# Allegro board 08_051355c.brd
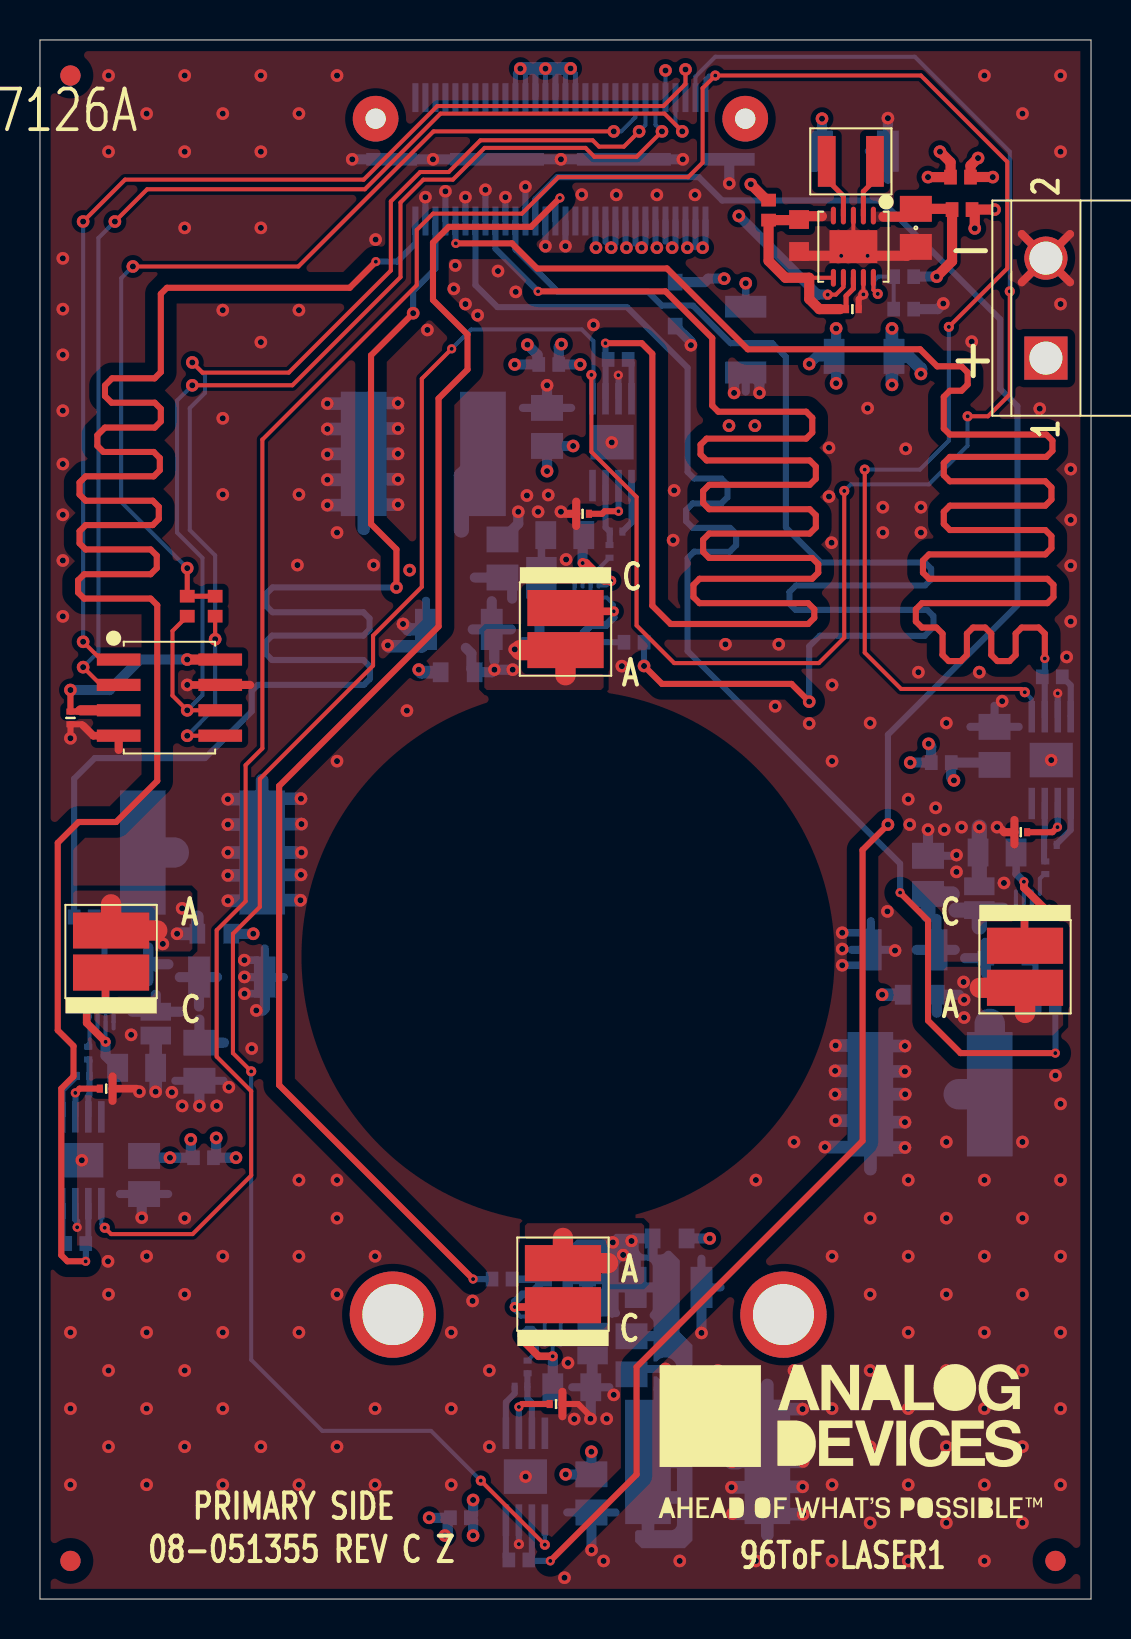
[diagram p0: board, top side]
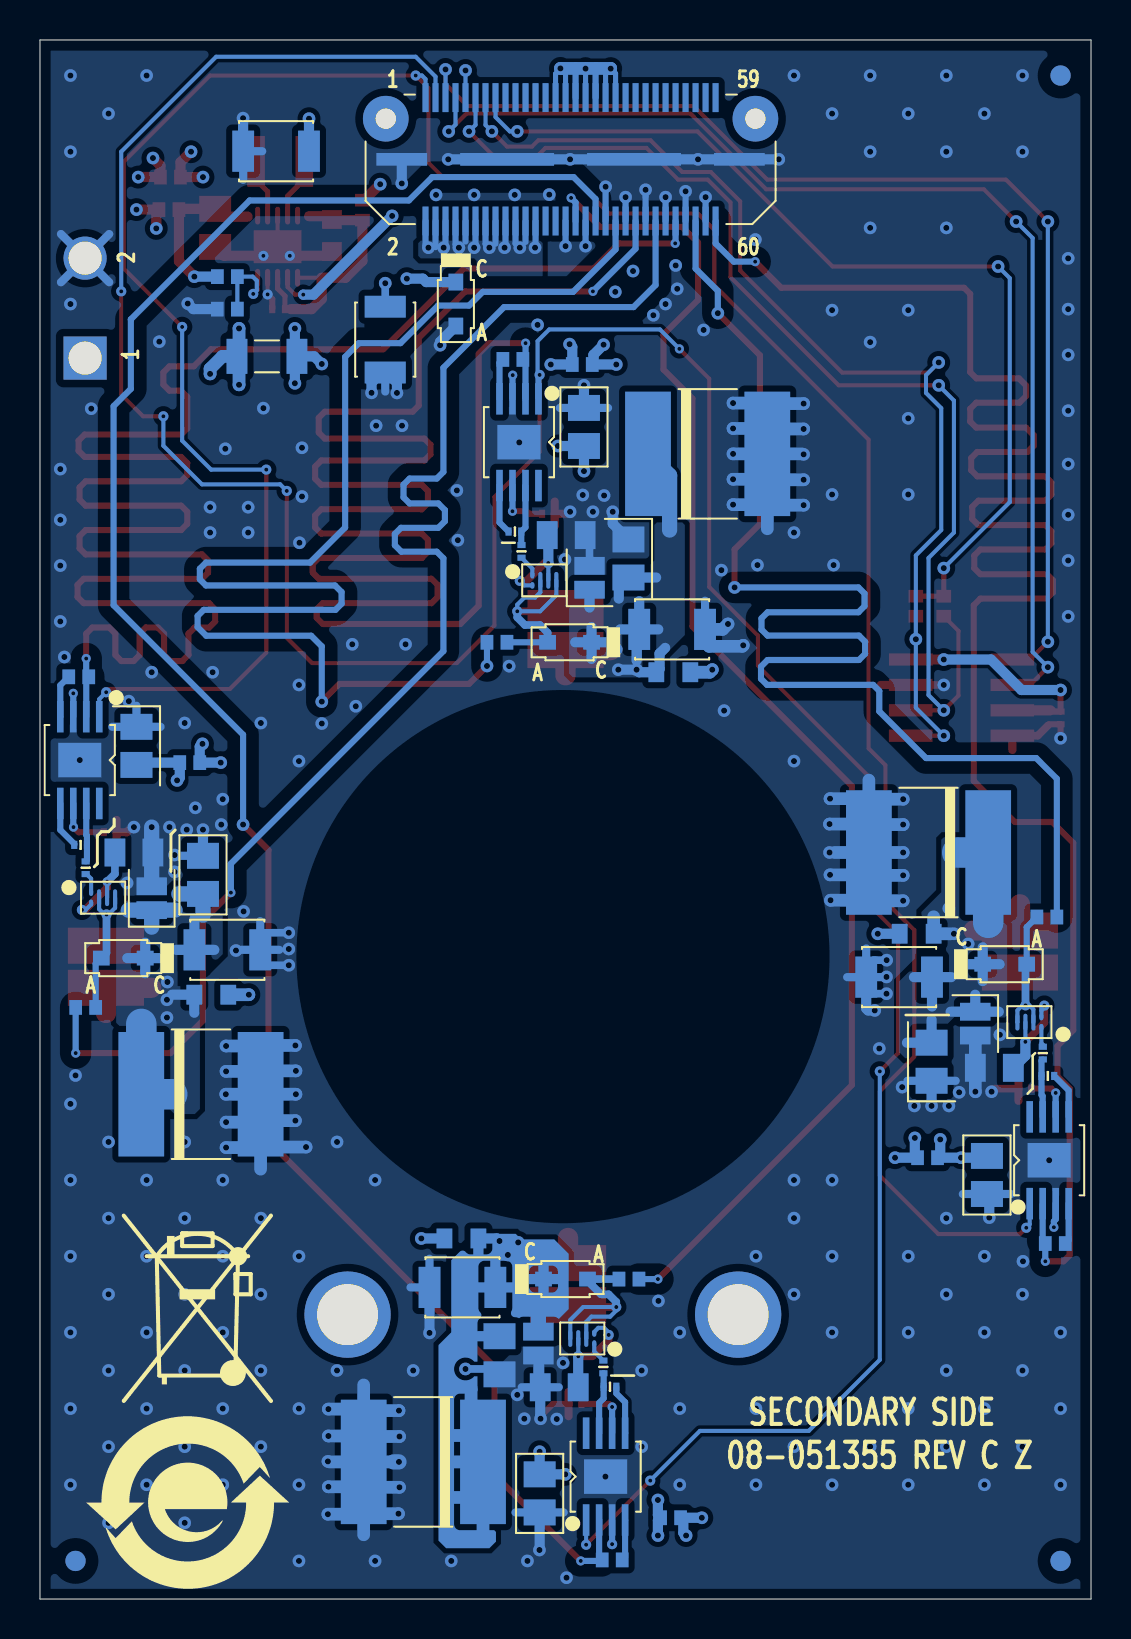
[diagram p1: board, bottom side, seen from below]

Outline 52.58 x 77.98 mm; copper layers: TOP, L2_GND, L3_PWR, L4_PWR, L5_GND, BOTTOM. Coordinates in mm from the lower left corner of the outline.
Outline path: 0,77.98 52.58,77.98 52.58,0 0,0 0,77.98

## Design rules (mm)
constraint set DEFAULT: min track width 0.203
net group TAL: nets TAL1 TAL2 TAL3 TAL4

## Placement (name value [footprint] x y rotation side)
C1  0.1uF  [C0201]  3.31 25.53 180 top
C2  0.1uF  [C0201]  25.82 9.75 180 top
C3  4.7UF  [C0805H53]  5.21 21.21 90 bottom
C4  4.7UF  [C0805H53]  27.58 5.28 90 bottom
C5  22NF  [C0306]  5.79 28.78 90 bottom
C6  22NF  [C0306]  27.65 12.78 90 bottom
C7  0.1uF  [C0201]  27.14 54.28 0 top
C8  0.1uF  [C0201]  49.06 38.35 0 top
C9  22UF  [C1210H106]  9.6 31.1 180 bottom
C10  22UF  [C1210H106]  31.45 15.59 180 bottom
C11  4.7UF  [C0805H53]  25.37 58.62 270 bottom
C12  4.7UF  [C0805H53]  47.75 42.67 270 bottom
C13  22UF  [C1210H106]  20.96 48.5 0 bottom
C14  22NF  [C0306]  25.09 51.08 270 bottom
C15  22UF  [C1210H106]  43.21 32.47 0 bottom
C16  22NF  [C0306]  46.99 35.05 270 bottom
C18  22UF  [C1210H106]  35.31 62.99 90 bottom
C19  22UF  [C1210H106]  40.77 72.42 180 bottom
C20  470UF  [C7260]  8.13 37.34 0 bottom
C21  470UF  [C7260]  44.53 25.25 180 bottom
C22  470UF  [C7260]  33.4 6.86 0 bottom
C23  470UF  [C7260]  19.18 57.28 180 bottom
C24  10uF  [C0603]  37.97 68.2 90 top
C25  0.1uF  [C0201]  40.64 64.52 0 top
C26  22UF  [C0805H60]  43.81 68.58 90 top
C27  4.7UF  [C0805H53]  7.98 26.87 90 bottom
C28  4.7UF  [C0805H53]  44.42 36.22 270 bottom
C29  4.7UF  [C0805H53]  29.59 12.19 90 bottom
C30  4.7UF  [C0805H53]  23.14 52.04 270 bottom
C31  0.1uF  [C0201]  1.52 44.07 90 top
D5  PLZ13B-G3/H  [DO219AC]  4.32 31.75 180 bottom
D6  PLZ13B-G3/H  [DO219AC]  26.29 16 180 bottom
D8  PLZ13B-G3/H  [DO219AC]  31.78 64.77 270 bottom
D9  PLZ13B-G3/H  [DO219AC]  26.09 47.85 0 bottom
D10  PLZ13B-G3/H  [DO219AC]  48.41 32.05 0 bottom
L1  1.5UH  [L1008_A]  40.56 71.91 0 top
LD1  I940-G2332-NBC-D1-60B45R  [VCSEL2_3_5X3_5]  3.56 32.38 90 top
LD2  I940-G2332-NBC-D1-60B45R  [VCSEL2_3_5X3_5]  49.28 31.62 270 top
LD3  I940-G2332-NBC-D1-60B45R  [VCSEL2_3_5X3_5]  26.29 48.51 270 top
LD4  I940-G2332-NBC-D1-60B45R  [VCSEL2_3_5X3_5]  26.16 15.75 90 top
NOREF  -  []  -34.29 -74.04 0 top
NOREF#2  -  []  52.58 0 90 top
NOREF#3  -  []  52.58 0 90 top
NOREF#4  -  []  -152.4 -254 0 top
NOREF#5  -  []  119.38 127 0 top
NOREF#6  -  []  0 77.98 270 top
NOREF#7  -  []  0 0 0 top
NOREF#8  -  [unnamed#2]  17.65 14.22 0 top
NOREF#9  -  []  40.56 7.87 0 top
NOREF#10  -  []  0 0 0 top
NOREF#11  -  []  206.43 -47.55 0 top
NOREF#12  -  []  215.9 215.9 0 top
NOREF#13  -  []  0 77.98 0 top
NOREF#14  -  [unnamed#2]  50.8 1.91 0 top
NOREF#15  -  [unnamed#2]  37.19 14.22 0 top
NOREF#16  -  []  17.45 40.6 0 top
NOREF#17  -  [unnamed#2]  1.52 1.91 0 top
NOREF#18  -  []  226.11 -117.6 0 top
NOREF#19  -  []  52.7 77.98 180 top
NOREF#20  -  []  -170.05 -267.97 0 top
NOREF#21  -  []  1.52 1.91 0 top
NOREF#22  -  []  26.57 98.68 0 top
NOREF#23  -  []  1.81 32.19 0 top
NOREF#24  -  []  0 77.98 0 top
NOREF#25  -  []  0 0 0 top
NOREF#26  -  [unnamed#2]  1.52 76.2 0 top
NOREF#27  -  []  26.42 32.13 0 top
NOREF#28  -  []  26.42 32.13 0 top
NOREF#29  -  []  1.52 1.91 0 top
NOREF#30  -  []  52.58 0 0 top
NOREF#31  -  []  201.92 -58.42 0 top
NOREF#32  -  [unnamed#2]  1.52 76.2 180 bottom
NOREF#33  -  [unnamed#2]  50.8 1.91 180 bottom
NOREF#34  -  [unnamed#2]  1.52 1.91 180 bottom
NOREF#35  -  []  35.43 22.86 180 bottom
NOREF#36  -  []  45.19 4.83 180 bottom
P1  QTH-030-03-L-D-A  [CNSAMTECQTH-030-03-X-D-A]  26.04 72.01 180 bottom
P2  Z5.530.3225.0  [CNWIELAND3225]  50.32 62.07 90 top
Q1  EPC2014C  [EPCX014X]  3.08 28.85 90 bottom
Q2  EPC2014C  [EPCX014X]  25.45 13.03 90 bottom
Q3  EPC2014C  [EPCX014X]  27.35 50.95 270 bottom
Q4  EPC2014C  [EPCX014X]  49.42 35.08 270 bottom
R1  0  [R0402]  1.79 17.78 180 bottom
R2  0  [R0402]  23.95 1.96 180 bottom
R3  0.33  [R0805]  4.84 26.57 180 bottom
R4  0.33  [R0805]  26.6 10.59 180 bottom
R5  0  [R0603]  8.72 33.27 180 bottom
R6  0  [R0603]  31.5 18.03 180 bottom
R7  4.7  [R0201]  2.41 27.3 90 bottom
R8  4.7  [R0201]  24.39 11.61 90 bottom
R9  0  [R0402]  28.92 62 0 bottom
R10  0  [R0402]  50.64 46.13 0 bottom
R11  0  [R0603]  20.9 46.36 0 bottom
R12  4.7  [R0201]  28.49 52.4 270 bottom
R13  0  [R0603]  44.01 30.23 0 bottom
R14  4.7  [R0201]  50.29 36.58 270 bottom
R15  0.33  [R0805]  26.25 53.21 0 bottom
R16  0.33  [R0805]  47.88 37.34 0 bottom
R22  0  [R1206]  41.22 62.15 0 bottom
R25  50  [R0402]  2.21 34.11 180 bottom
R26  50  [R0402]  50.29 29.59 0 bottom
R29  50  [R0402]  23.11 16 180 bottom
R30  50  [R0402]  29.72 47.85 0 bottom
R31  0  [R0402]  8.18 22.07 180 bottom
R32  0  [R0402]  45.09 41.83 0 bottom
R33  0  [R0402]  21.03 4.06 0 bottom
R34  0  [R0402]  25.45 61.75 0 bottom
R35  0  [R0402]  43.21 64.52 180 bottom
R36  0  [R0402]  36.45 69.47 90 top
R37  0  [R0402]  43.21 66.14 0 bottom
R38  0  [R0402]  46.05 71.12 180 top
R39  0  [R0402]  46.13 69.49 0 top
R40  10K  [R0402]  8.76 49.66 270 top
R41  10K  [R0402]  7.37 49.66 270 top
R42  0  [R0201]  2.16 26.16 0 bottom
R43  0  [R0201]  50.55 37.72 180 bottom
R44  0  [R0201]  24.06 10.62 0 bottom
R45  0  [R0201]  28.82 53.39 180 bottom
U1  ADP3624ARHZ  [MSOP8_PAD2_16X1_73]  2.09 21.95 180 bottom
U2  ADP3624ARHZ  [MSOP8_PAD2_16X1_73]  24.28 6.12 180 bottom
U3  ADP3624ARHZ  [MSOP8_PAD2_16X1_73]  28.62 57.86 0 bottom
U4  ADP3624ARHZ  [MSOP8_PAD2_16X1_73]  50.59 41.96 0 bottom
U5  ADP2504ACPZ-5.0  [DFN10_3X3_PAD2_38X1_64]  40.69 67.64 180 top
U6  ADT7410TRZ  [SO8]  6.48 45.09 270 top

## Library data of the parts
C1 C2 C7 C8 C25 C31 = CAP: Tolerance: 20; User Part Number: UPN; alternate symbols: (); part number: CAP_SM-0.1UF,16V,20,E017331,C0201; tolerance: 20
C3 C4 C11 C12 C27-C30 = CAP: Tolerance: 10; User Part Number: UPN; alternate symbols: (); part number: CAP_SM-4.7UF,25V,10,E025752,C0805H53; tolerance: 10
C5 C6 C14 C16 = CAP: Tolerance: 20; User Part Number: UPN; alternate symbols: (); part number: CAP_SM-22NF,16V,20,E034159,C0306; tolerance: 20
C9 C10 C13 C15 C18 C19 = CAP: Tolerance: 10; User Part Number: UPN; alternate symbols: (); part number: CAP_SM-22UF,25V,10,E025745,C1210H106; tolerance: 10
C20-C23 = CAPP: Tolerance: 10; User Part Number: UPN; alternate symbols: (); part number: CAPP_SM-470UF,10V,10,E027243,C7260; tolerance: 10
C24 = CAP: User Part Number: UPN; Tolerance: 20; alternate symbols: (); part number: CAP_SM-10UF,6.3V,20,E007143,C0603; tolerance: 20
C26 = CAP: Tolerance: 20; User Part Number: UPN; alternate symbols: (); part number: CAP_SM-22UF,10V,20,E032369,C0805H60; tolerance: 20
D5 D6 D8-D10 = DIOZNR: User Part Number: UPN; Tolerance: 2; alternate symbols: (); part number: DIOZNR_SM-PLZ13B-G3/H,13V,2,E025186,DO219AC; tolerance: 2
L1 = IND: Tolerance: 20; User Part Number: UPN; alternate symbols: (); part number: IND_SM-1.5UH,20,E026128,L1008_A; tolerance: 20
LD1-LD4 = DIOLASER: User Part Number: UPN; Tolerance: N/A; alternate symbols: (); part number: DIOLASER_SM-I940-G2332-NBC-D1-110B85R,5V,N/A,E035420,VCSEL2_3_5X3_5; tolerance: N/A
P1 = CN60P_ODD_EVEN_4GND: User Part Number: UPN; Tolerance: N/A; alternate symbols: (); part number: CN60P_ODD_EVEN_4GND_SM-QTH-030-03-L-D-A,E035156,CNSAMTECQTH-030-03-X-D-A; tolerance: N/A
P2 = CN2P: User Part Number: UPN; Tolerance: N/A; alternate symbols: (); part number: CN2P_TH-Z5.530.3225.0,E008161,CNWIELAND3225; tolerance: N/A
Q1-Q4 = TRANNGANFET: Tolerance: N/A; User Part Number: UPN; alternate symbols: (); part number: TRANNGANFET_SM-EPC2014C,E023055,EPCX014X; tolerance: N/A
R1 R2 R9 R10 R31-R39 = RES: User Part Number: UPN; Tolerance: 5; alternate symbols: (R0402L,R0402L_ALT); part number: RES_SM-0,E003438,N/A,5,R0402; tolerance: 5
R3 R4 R15 R16 = RES: User Part Number: UPN; Tolerance: 1; alternate symbols: (R0805L); part number: RES_SM-0.33,E013321,1/8W,1,R0805; tolerance: 1
R5 R6 R11 R13 = RES: User Part Number: UPN; Tolerance: 5; alternate symbols: (R0603L); part number: RES_SM-0,E006826,1/10W,5,R0603; tolerance: 5
R7 R8 R12 R14 = RES: Tolerance: 5; User Part Number: UPN; alternate symbols: (); part number: RES_SM-4.7,E019116,1/20W,5,R0201; tolerance: 5
R22 = RES: User Part Number: UPN; Tolerance: N/A; alternate symbols: (); part number: RES_SM-0,E014206,1/2W,N/A,R1206; tolerance: N/A
R25 R26 R29 R30 = RES: User Part Number: UPN; Tolerance: 0.1; alternate symbols: (R0402L); part number: RES_SM-50,E016309,1/20W,0.1,R0402; tolerance: 0.1
R40 R41 = RES: User Part Number: UPN; Tolerance: 5; alternate symbols: (R0402L); part number: RES_SM-10K,E017176,1/10W,5,R0402; tolerance: 5
R42-R45 = RES: Tolerance: N/A; User Part Number: UPN; alternate symbols: (); part number: RES_SM-0,E004015,1/20W,0,R0201; tolerance: N/A
U1-U4 = ADP36X4: Tolerance: N/A; User Part Number: UPN; alternate symbols: (); part number: ADP36X4_SM-ADP3624ARHZ,E025682,MSOP8_PAD2_16X1_73; tolerance: N/A
U5 = ADP250X: Tolerance: N/A; User Part Number: UPN; alternate symbols: (); part number: ADP250X_SM-ADP2504ACPZ-5.0,E033974,DFN10_3X3_PAD2_38X1_64; tolerance: N/A
U6 = ADT7410: Tolerance: N/A; User Part Number: UPN; alternate symbols: (); part number: ADT7410_SM-ADT7410TRZ,E010871,SO8; tolerance: N/A

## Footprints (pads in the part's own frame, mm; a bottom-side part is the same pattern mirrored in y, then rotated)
C0201
  rect 0.305x0.406 smd: 1(-0.318,0) 2(0.318,0)
C0306
  rect 0.889x1.524 smd: 1(-0.597,0) 2(0.597,0)
C0603
  rect 0.94x0.991 smd: 1(-0.8,0) 2(0.8,0)
C0805H53
  rect 1.295x1.6 smd: 1(-0.953,0) 2(0.953,0)
C0805H60
  rect 1.295x1.6 smd: 1(-0.953,0) 2(0.953,0)
C1210H106
  rect 1.092x2.057 smd: 1(-1.646,0) 2(1.646,0)
C7260
  rect 2.286x6.223 smd: N(2.985,0) P(-2.985,0)
CNSAMTECQTH-030-03-X-D-A
  round 2.286 hole 1.016 unplated: (-9.246,2.032) (9.246,2.032)
  rect 0.305x1.448 smd: 1(-7.257,3.086) 2(-7.257,-3.086) 3(-6.756,3.086) 4(-6.756,-3.086) 5(-6.256,3.086) 6(-6.256,-3.086) 7(-5.756,3.086) 8(-5.756,-3.086) 9(-5.255,3.086) 10(-5.255,-3.086) 11(-4.755,3.086) 12(-4.755,-3.086) 13(-4.255,3.086) 14(-4.255,-3.086) 15(-3.754,3.086) 16(-3.754,-3.086) 17(-3.254,3.086) 18(-3.254,-3.086) 19(-2.753,3.086) 20(-2.753,-3.086) 21(-2.253,3.086) 22(-2.253,-3.086) 23(-1.753,3.086) 24(-1.753,-3.086) 25(-1.252,3.086) 26(-1.252,-3.086) 27(-0.752,3.086) 28(-0.752,-3.086) 29(-0.251,3.086) 30(-0.251,-3.086) 31(0.249,3.086) 32(0.249,-3.086) 33(0.749,3.086) 34(0.749,-3.086) 35(1.25,3.086) 36(1.25,-3.086) 37(1.75,3.086) 38(1.75,-3.086) 39(2.25,3.086) 40(2.25,-3.086) 41(2.751,3.086) 42(2.751,-3.086) 43(3.251,3.086) 44(3.251,-3.086) 45(3.752,3.086) 46(3.752,-3.086) 47(4.252,3.086) 48(4.252,-3.086) 49(4.752,3.086) 50(4.752,-3.086) 51(5.253,3.086) 52(5.253,-3.086) 53(5.753,3.086) 54(5.753,-3.086) 55(6.253,3.086) 56(6.253,-3.086) 57(6.754,3.086) 58(6.754,-3.086) 59(7.254,3.086) 60(7.254,-3.086)
  rect 2.54x0.635 smd: PAD1(-8.445,0) PAD4(8.445,0)
  rect 4.699x0.635 smd: PAD2(-3.175,0) PAD3(3.175,0)
CNWIELAND3225
  rect 2.159x2.159 hole 1.651: 1(0,0)
  round 2.159 hole 1.651: 2(5,0)
DFN10_3X3_PAD2_38X1_64
  oval 0.254x0.889 smd: 1(-1,-1.555) 2(-0.5,-1.555) 3(0,-1.555) 4(0.5,-1.555) 5(1,-1.555) 6(1,1.555) 7(0.5,1.555) 8(0,1.555) 9(-0.5,1.555) 10(-1,1.555)
  rect 2.388x1.651 smd: PAD(0,0)
DO219AC
  rect 0.838x0.737 smd: A(1.1,0) C(-1.1,0)
EPCX014X
  oval 0.33x0.203 smd: 1(-0.253,-0.601) 2(0.253,-0.601)
  oval 0.838x0.203 smd: 3(0,-0.201) 4(0,0.199) 5(0,0.599)
L1008_A
  rect 0.889x2.54 smd: 1(-1.206,0) 2(1.206,0)
MSOP8_PAD2_16X1_73
  rect 0.33x1.575 smd: 1(-0.975,-2.171) 2(-0.325,-2.171) 3(0.325,-2.171) 4(0.975,-2.171) 5(0.975,2.171) 6(0.325,2.171) 7(-0.325,2.171) 8(-0.975,2.171)
  rect 2.159x1.727 smd: PAD(0,0)
R0201
  rect 0.305x0.406 smd: 1(-0.318,0) 2(0.318,0)
R0402
  rect 0.635x0.737 smd: 1(-0.5,0) 2(0.5,0)
R0603
  rect 0.787x0.991 smd: 1(-0.85,0) 2(0.85,0)
R0805
  rect 1.041x1.397 smd: 1(-0.95,0) 2(0.95,0)
R1206
  rect 1.041x1.753 smd: 1(-1.5,0) 2(1.5,0)
SO8
  rect 0.61x2.184 smd: 1(-1.905,-2.54) 2(-0.635,-2.54) 3(0.635,-2.54) 4(1.905,-2.54) 5(1.905,2.54) 6(0.635,2.54) 7(-0.635,2.54) 8(-1.905,2.54)
unnamed#2
  round 4.318 hole 3.048 unplated: (0,0)
VCSEL2_3_5X3_5
  rect 1.803x3.81 smd: A(1.052,0) C(-1.052,0)

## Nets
5V_LD: R31.1 R32.1 R33.1 R34.1 R38.1 R39.2(N2)
5VDD_CON: C19.2(N2) P1.27 P1.29 P1.31 P1.33 P1.35 P1.37 P1.39 R36.2(N2) R38.2(N2) U5.7
AGND: C1.1 C2.1 C3.1 C4.1 C5.1 C6.1 C7.1 C8.1 C9.1 C10.1 C11.1 C12.1 C13.1 C14.1 C15.1 C16.1 C18.1 C19.1 C20.N(N2) C21.N(N2) C22.N(N2) C23.N(N2) C24.1 C25.2(N2) C26.1 C27.1 C28.1 C29.1 C30.1 C31.1 D8.A(P) P1.30 P1.34 P1.38 P1.42 P1.46 P1.50 P1.54 P1.58 P1.PAD1 P1.PAD2 P1.PAD3 P1.PAD4 P2.2(N2) R3.1 R4.1 R15.1 R16.1 R35.1 U1.3 U1.PAD U2.3 U2.PAD U3.3 U3.PAD U4.3 U4.PAD U5.3 U5.9 U5.PAD U6.4 U6.7
3P3VDD: C31.2(N2) P1.9 U6.3 U6.8(VDD)
CT_LASER: P1.11 R41.2(N2) U6.6
DS1: C5.2(N2) C9.2(N2) C20.P C27.2(N2) D5.C LD1.A R5.2(N2)
DS2: C15.2(N2) C16.2(N2) C21.P C28.2(N2) D10.C LD2.A R13.2(N2)
DS3: C13.2(N2) C14.2(N2) C23.P C30.2(N2) D9.C LD3.A R11.2(N2)
DS4: C6.2(N2) C10.2(N2) C22.P C29.2(N2) D6.C LD4.A R6.2(N2)
I2C0_SCL: P1.5 U6.1
I2C0_SDA: P1.7 U6.2
INT_LASER: P1.13 R40.2(N2) U6.5
IOVDD: P1.15 R40.1 R41.1
LD1: P1.60 R1.1 U1.2
LD2: P1.52 R10.1 U4.2
LD3: P1.44 R9.1 U3.2
LD4: P1.36 R2.1 U2.2
LD_SD1: P1.1 U1.1 U4.1
LD_SD2: P1.3 U2.1 U3.1
LD_SUPPLY: P2.1 R5.1 R6.1 R11.1 R13.1 R22.2(N2)
TAL1: P1.56 R25.2(N2)
TAL2: P1.48 R26.2(N2)
TAL3: P1.40 R30.2(N2)
TAL4: P1.32 R29.2(N2)
UNNAMED_4_ADP36X4_I6_INB: R1.2(N2) U1.4
UNNAMED_4_ADP36X4_I6_OUTA: R7.1 R42.2(N2) U1.7
UNNAMED_4_ADP36X4_I6_OUTB: R42.1 U1.5
UNNAMED_4_ADP36X4_I6_VDD: C1.2(N2) C3.2(N2) R31.2(N2) U1.6(VDD)
UNNAMED_4_ADP36X4_I26_INB: R2.2(N2) U2.4
UNNAMED_4_ADP36X4_I26_OUTA: R8.1 R44.2(N2) U2.7
UNNAMED_4_ADP36X4_I26_OUTB: R44.1 U2.5
UNNAMED_4_ADP36X4_I26_VDD: C2.2(N2) C4.2(N2) R33.2(N2) U2.6(VDD)
UNNAMED_4_ADP36X4_I59_INB: R9.2(N2) U3.4
UNNAMED_4_ADP36X4_I59_OUTA: R12.1 R45.2(N2) U3.7
UNNAMED_4_ADP36X4_I59_OUTB: R45.1 U3.5
UNNAMED_4_ADP36X4_I59_VDD: C7.2(N2) C11.2(N2) R34.2(N2) U3.6(VDD)
UNNAMED_4_ADP36X4_I77_INB: R10.2(N2) U4.4
UNNAMED_4_ADP36X4_I77_OUTA: R14.1 R43.2(N2) U4.7
UNNAMED_4_ADP36X4_I77_OUTB: R43.1 U4.5
UNNAMED_4_ADP36X4_I77_VDD: C8.2(N2) C12.2(N2) R32.2(N2) U4.6(VDD)
UNNAMED_4_ADP250X_I213_EN: C24.2(N2) C25.1 R36.1 U5.5 U5.6 U5.8
UNNAMED_4_ADP250X_I213_FB: R35.2(N2) R37.1 U5.10
UNNAMED_4_ADP250X_I213_SW1: L1.1 U5.4
UNNAMED_4_ADP250X_I213_SW2: L1.2(N2) U5.2
UNNAMED_4_ADP250X_I213_VOUT: C26.2(N2) R37.2(N2) R39.1 U5.1(VOUT)
UNNAMED_4_DIOZNR_I124_P: D5.A(P) LD1.C Q1.3 Q1.5 R25.1
UNNAMED_4_DIOZNR_I125_P: D6.A(P) LD4.C Q2.3 Q2.5 R29.1
UNNAMED_4_DIOZNR_I126_P: D10.A(P) LD2.C Q4.3 Q4.5 R26.1
UNNAMED_4_DIOZNR_I127_P: D9.A(P) LD3.C Q3.3 Q3.5 R30.1
UNNAMED_4_RES_I11_N2: Q1.1 R7.2(N2)
UNNAMED_4_RES_I44_N2: Q2.1 R8.2(N2)
UNNAMED_4_RES_I53_N2: Q1.2(SUBSTRATE) Q1.4 R3.2(N2)
UNNAMED_4_RES_I54_N2: Q2.2(SUBSTRATE) Q2.4 R4.2(N2)
UNNAMED_4_RES_I70_N2: Q3.2(SUBSTRATE) Q3.4 R15.2(N2)
UNNAMED_4_RES_I73_N2: Q3.1 R12.2(N2)
UNNAMED_4_RES_I87_N2: Q4.2(SUBSTRATE) Q4.4 R16.2(N2)
UNNAMED_4_RES_I90_N2: Q4.1 R14.2(N2)
VLD_BRD: C18.2(N2) D8.C P1.2 P1.4 P1.6 P1.8 P1.10 P1.12 P1.14 P1.16 P1.18(N9) P1.20 P1.22 P1.24 R22.1

Pads without a net: P1 17 19 21 23 25 26 28 41 43 45 47 49 51 53 55 57 59; U1 8; U2 8; U3 8; U4 8

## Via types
v1: diameter 0.635, hole 0.305, TOP to BOTTOM, 366 vias
v2: diameter 0.508, hole 0.203, TOP to BOTTOM, 29 vias
v3: diameter 0.457, hole 0.203, TOP to BOTTOM, 20 vias

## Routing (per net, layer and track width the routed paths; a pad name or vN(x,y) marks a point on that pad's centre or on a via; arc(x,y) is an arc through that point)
5V_LD: length 13.1
  TOP w0.508: v1(47.75,69.49) R39.2 46.76,69.36 v1(46.76,68.55) ; v1(47.66,71.12) 47.66,71.13 46.56,71.13 R38.1 46.55,71.7 v1(46.93,72.07)
  BOTTOM w0.508: v1(24.38,62.74) 24.89,62.23 24.89,61.81 R34.1 v1(23.75,61.75) ; v1(19.47,4.06) R33.1 20.4,3.93 20.4,3.31 v1(20.26,3.17) ; v1(43.54,41.83) R32.1 44.59,42.64 v1(44.45,42.77) ; v1(8.81,23.06) 8.81,22.21 R31.1 v1(9.8,22.07)
5VDD_CON: length 26.1
  TOP w0.203: U5.7 40.19,65.62 39.81,65.24 v2(39.41,65.24)
  TOP w0.508: v1(35.56,70.76) 36.36,69.97 R36.2 ; v1(44.42,71.12) R38.2 45.55,71.86 v1(45.02,72.39)
  BOTTOM w0.254: P1.33 v1(25.29,76.55) ; 26.54,76.53 26.79,76.29 P1.27 ; 26.54,76.53 26.29,76.27 P1.29 ; 26.54,76.53 v1(26.54,76.56) ; P1.37 24.28,76.29 v1(24.03,76.55) 23.78,76.3 P1.39
  BOTTOM w0.305: 24.77,76.56 24.79,76.54 P1.35 ; P1.31 25.79,76.55 25.78,76.56
  BOTTOM w0.508: C19.2 v1(39.12,74.04) ; v1(34.96,69.18) 38.9,65.24 v2(39.41,65.24)
  BOTTOM w0.635: v1(26.54,76.56) 24.03,76.56 v1(24.03,76.55)
AGND: length 248.9
  TOP w0.203: U5.3 U5.PAD ; U5.9 v2(41.19,65.25)
  TOP w0.305: C2.1 26.92,9.75 27.53,9.14 27.53,9.02 v1(27.54,9.02) ; v1(1.52,43.05) C31.1 2.1,43.75 2.16,43.69 ; C25.2 40.96,65.02 41.14,65.2
  TOP w0.381: v1(46.99,38.61) 47.07,38.53 ; 3.94,43.18 2.67,43.18 2.16,43.69 ; v1(4.97,25.37) 4.82,25.53 C1.1 ; U6.7 v1(7.37,45.72) ; 41.14,65.2 v2(41.19,65.25)
  TOP w0.406: U6.7 10.52,45.72 ; v1(47.88,38.61) 47.98,38.61 48.23,38.35 C8.1 ; 49.12,68.27 P2.2 ; P2.2 51.53,68.27 ; P2.2 49.12,65.86 ; P2.2 51.53,65.86 ; 26.13,10.36 C2.1 26.13,9.14 ; C8.1 48.75,37.74 ; C8.1 48.75,38.96 ; 3.63,26.14 C1.1 3.63,24.92 ; 26.27,54.28 C7.1 ; C7.1 26.83,53.67 ; C7.1 26.83,54.89 ; 3.94,42.47 3.94,43.18
  TOP w0.508: C24.1 38.19,67.18 v2(40.08,67.18) ; v2(41.4,67.18) 43.37,67.18 C26.1
  BOTTOM w0.305: v1(22.28,70.48) 22.28,70.14 P1.46 ; P1.50 v1(21.28,70.12) ; P1.58 v1(19.28,70.12) ; P1.42 v1(23.28,70.12) ; v1(24.28,70.64) 24.28,70.63 P1.38 ; v3(28.93,61.21) 28.94,61.2 U3.3 ; U2.3 v2(23.96,2.74) ; P1.34 v1(25.29,67.67) ; P1.54 v1(20.28,70.41) ; v3(1.86,18.59) 1.86,18.89 1.77,18.98 U1.3 ; P1.30 v1(26.29,67.67) ; U4.3 v3(50.91,45.3)
  BOTTOM w0.381: v1(31.29,11.51) 29.86,11.51 C29.1 ; 25.3,53.22 R15.1 25.09,52.99 C14.1 ; 11.25,30.53 10.99,30.28 v1(10.23,30.28) 10.27,30.23 ; v1(40.13,33.32) 41.33,33.32 41.56,33.1 ; v1(40.13,31.7) 41.18,31.7 41.56,32.08 ; v1(10.22,31.95) 10.87,31.95 11.25,31.57
  BOTTOM w0.406: P2.2 51.53,65.86 ; P2.2 51.53,68.27 ; P2.2 49.12,65.86 ; P2.2 49.12,68.27 ; 41.56,33.91 41.56,33.1 ; 26.57,59.58 C11.1 24.16,59.58 ; 35.31,60.39 C18.1 ; 41.46,72.42 C19.1 ; C19.1 42.41,70.98 ; C19.1 42.41,73.85 ; C9.1 11.25,32.54 ; C9.1 10.29,31.1 ; C9.1 12.2,31.1 ; 33.09,17.02 C10.1 34.04,15.59 ; R4.1 27.55,11.7 ; R4.1 26.63,10.59 ; R4.1 28.48,10.59 ; 41.56,32.08 C15.1 ; C15.1 40.61,32.47 ; C15.1 42.51,32.47 ; C13.1 19.31,49.93 ; C12.1 48.96,43.62 ; C12.1 47.75,44.68 ; C12.1 46.55,43.62 ; 6.77,25.92 C27.1 9.18,25.92 ; 4,20.26 C3.1 6.41,20.26 ; 28.79,4.33 C4.1 26.38,4.33 ; C28.1 45.63,37.17
  BOTTOM w0.508: v1(42.42,74.07) 42.42,72.42 C19.1 ; R35.1 44.91,64.52 v1(45.19,64.8) ; D8.A 32.56,62.88 v1(32.56,62.71) ; C4.1 27.58,2.47 27.59,2.46 v1(27.59,2.45) ; C30.1 23.93,53.78 v1(23.93,54.38) ; C10.1 v1(33.09,13.31) ; v1(35.99,60.33) 35.99,60.84 35.48,61.35 C18.1 35.23,61.35 34.72,60.84 v1(34.72,60.33) ; P1.PAD1 v1(34.48,70.8) ; v1(15.62,72.01) P1.PAD4 v1(19.66,72.01) P1.PAD3 v1(26.06,72.01) P1.PAD2 v1(32.16,72.01) ; v1(10.82,29.44) 11.15,29.44 11.25,29.54 C9.1 ; v1(27.54,9.02) 27.54,9.15 27.55,9.16 R4.1 27.65,10.68 C6.1 ; C3.1 5.21,20.07 5.09,19.95 v1(5.09,19.08) ; C28.1 v1(44.42,38.48) ; v1(25.37,60.71) C11.1 ; C27.1 v1(7.98,24.66)
  BOTTOM w0.635: v1(38.15,5.61) 37.03,5.61 36.39,6.26 ; 16.19,55.12 15.79,54.71 v1(14.38,54.71) ; 16.19,55.12 16.19,53.53 ; 16.19,55.12 16.57,54.74 v1(17.91,54.74) ; 16.19,55.12 16.19,56.52 ; v1(9.4,36.2) 10.6,36.2 11.11,36.7 ; v1(38.18,4.24) 36.84,4.24 36.39,4.7 ; C22.N 36.39,7.51 ; C22.N 36.39,6.26 ; C22.N 38.1,6.86 ; C22.N 34.89,6.86 ; 36.39,7.51 36.39,7.62 ; 36.39,7.51 37.03,8.15 v1(38.15,8.15) ; 41.54,27.09 40.94,27.69 v1(39.8,27.69) ; 41.54,27.09 41.54,25.88 ; 41.54,27.09 42.11,27.66 v1(43.27,27.66) ; 36.39,6.26 36.39,6.1 ; 36.39,6.1 35.88,5.59 v1(34.59,5.59) ; 36.39,6.1 36.39,4.7 ; 36.39,7.62 36.39,8.79 ; 36.39,7.62 35.88,8.13 v1(34.59,8.13) ; 41.54,25.88 42.05,26.39 v1(43.27,26.39) ; 41.54,25.88 C21.N ; 41.54,25.88 41.01,26.42 v1(39.78,26.42) ; v1(38.15,9.5) 37.1,9.5 36.39,8.79 ; 11.11,38.13 C20.N ; 11.11,38.13 11.11,38.23 ; 11.11,38.13 11.75,38.76 v1(13.08,38.76) ; C20.N 12.83,37.34 ; C20.N 11.11,36.86 ; C20.N v1(9.4,37.34) ; v1(14.38,55.98) 15.66,55.98 16.19,56.52 ; 41.54,21.5 41.54,23.16 ; 41.54,23.16 41.54,24.36 ; 41.54,23.16 40.98,22.61 v1(39.27,22.61) ; 41.54,23.16 42.13,22.58 v1(43.27,22.58) ; v1(18.16,48.77) 18.43,48.5 C13.1 19.31,47.86 19.1,47.65 17.45,47.65 v1(17.4,47.7) ; 11.11,38.23 11.11,39.55 ; 11.11,38.23 10.6,38.73 v1(9.4,38.73) ; 11.11,39.55 10.66,40.01 v1(9.4,40.01) ; 11.11,39.55 11.11,40.96 ; 11.11,39.55 11.6,40.03 v1(13.06,40.03) ; 36.39,3.21 36.39,4.7 ; 36.39,4.7 35.95,4.27 v1(34.65,4.27) ; 41.54,24.36 41.11,23.93 v1(39.8,23.93) ; 41.54,24.36 C21.N ; 41.54,24.36 42.05,23.85 v1(43.27,23.85) ; 36.39,8.79 36.39,10.71 ; 36.39,8.79 35.75,9.42 v1(34.62,9.42) ; 11.11,36.7 11.11,36.86 ; 11.11,36.7 11.11,35.59 ; 11.11,36.86 11.75,36.22 v1(13.06,36.22) ; 16.19,59.31 15.71,59.79 v1(14.38,59.79) ; 16.19,59.31 16.7,59.82 v1(17.91,59.82) ; 16.19,59.31 16.19,58.04 ; 16.19,56.52 16.7,56.01 v1(17.91,56.01) ; 16.19,56.52 C23.N ; v1(14.38,58.52) 15.71,58.52 16.19,58.04 ; 11.11,35.59 11.11,35.43 10.6,34.93 v1(9.4,34.93) ; 11.11,35.59 11.75,34.95 v1(13.03,34.95) ; C23.N 14.48,57.28 ; C23.N 16.19,58.04 ; C23.N v1(17.91,57.28) ; v1(5.79,25.37) R3.1 5.79,28.18 C5.1 ; 16.19,58.04 16.7,58.55 v1(17.91,58.55) ; C21.N v1(43.28,25.25) ; C21.N v1(39.78,25.25)
  BOTTOM w0.762: C16.1 46.99,37.28 R16.1 46.99,37.4 v1(46.99,38.61) ; 34.89,6.86 v1(34.62,6.86)
  vias: v1(1.14,67.06) v1(1.14,64.52) v1(1.14,62.23) v1(1.14,59.44) v1(1.14,56.77) v1(1.14,54.23) v1(1.14,51.94) v1(1.14,49.15) v1(1.52,13.33) v1(1.52,9.53) v1(1.52,5.71) v1(2.09,21.95) v1(3.43,76.2) v1(3.43,72.39) v1(3.4,16.89) v1(3.43,15.24) v1(3.43,11.43) v1(3.43,7.62) v1(4.56,28.22) v1(5.33,74.3) v1(5.33,17.14) v1(5.33,13.33) v1(5.33,9.53) v1(5.33,5.71) v1(6.6,25.34) v1(7.11,24.66) v1(7.24,76.2) v1(7.24,72.39) v1(7.24,68.58) v1(7.24,19.05) v1(7.24,15.24) v1(7.24,11.43) v1(7.24,7.62) v1(8.84,24.66) v1(9.14,74.3) v1(9.14,64.47) v1(9.14,59.05) v1(9.14,55.25) v1(9.14,17.14) v1(9.14,13.33) v1(9.14,9.53) v1(9.14,5.71) v1(9.45,25.6) v1(10.23,31.12) v1(10.59,27.53) v1(11.05,76.2) v1(11.05,72.39) v1(11.05,68.58) v1(11.05,62.87) v1(11.05,7.62) v1(12.95,74.3) v1(12.95,64.47) v1(12.95,55.25) v1(12.88,51.71) v1(12.95,20.96) v1(12.95,17.14) v1(12.95,13.33) v1(12.95,5.71) v1(13.08,37.34) v1(14.38,57.25) v1(14.86,76.2) v1(14.86,53.34) v1(14.86,41.91) v1(14.86,20.96) v1(14.86,19.05) v1(14.86,15.24) v1(14.86,7.62) v1(16.69,51.71) v1(16.76,17.14) v1(16.76,9.53) v1(16.76,5.71) v1(16.79,68) v1(18.36,44.43) v1(18.49,51.46) v1(19.38,63.47) v1(20.57,13.33) v1(20.57,9.53) v1(20.57,5.71) v1(20.7,65.53) v1(20.78,66.7) v1(21.29,64.77) v1(21.64,14.91) v1(21.89,64.21) v1(22.48,11.43) v1(22.48,7.62) v1(22.91,66.42) v1(23.8,65.38) v1(24.36,55.19) v1(24.29,6.12) v1(24.92,54.38) v1(25.43,55.22) v1(26.06,54.38) v1(26.24,1.07) v1(26.32,51.99) v1(26.41,11.81) v1(26.73,9) v1(27.1,70.24) v1(27.69,63.73) v1(28.19,1.91) v1(28.35,9.02) v1(28.6,57.85) v1(28.7,10.21) v1(28.83,70.23) v1(29.11,46.66) v1(30.86,70.23) v1(31.67,52.96) v1(31.72,55.45) v1(32,1.91) v1(32.77,70.23) v1(33.91,11.43) v1(34.29,47.75) v1(34.47,58.69) v1(35.76,58.69) v1(35.81,20.96) v1(35.81,1.91) v1(36.78,44.65) v1(36.96,47.75) v1(37.72,22.86) v1(37.72,11.43) v1(38.18,6.88) v1(38.48,43.79) v1(39.47,57.58) v1(39.47,55.14) v1(39.6,52.83) v1(39.62,45.72) v1(39.62,41.91) v1(39.62,17.14) v1(39.62,9.53) v1(39.62,5.71) v1(39.62,1.91) v1(40.13,32.51) v1(41.4,59.56) v1(41.53,43.81) v1(41.53,19.05) v1(41.53,15.24) v1(41.53,11.43) v1(41.53,7.62) v1(41.53,3.81) v1(42.16,54.61) v1(42.16,53.34) v1(42.39,34.39) v1(42.77,32.44) v1(43.31,57.53) v1(43.43,40.01) v1(43.43,20.96) v1(43.43,17.14) v1(43.43,13.33) v1(43.43,9.53) v1(43.43,5.71) v1(43.43,1.91) v1(43.51,38.73) v1(43.94,46.36) v1(44.07,54.61) v1(44.07,53.34) v1(44.81,39.57) v1(45.24,38.48) v1(45.34,43.81) v1(45.34,22.86) v1(45.34,19.05) v1(45.34,15.24) v1(45.34,11.43) v1(45.34,7.62) v1(45.34,3.81) v1(45.85,37.21) v1(45.85,36.37) v1(46.1,38.61) v1(46.61,62.89) v1(46.99,46.36) v1(47.24,76.2) v1(47.24,20.96) v1(47.24,17.14) v1(47.24,13.33) v1(47.24,9.53) v1(47.24,5.71) v1(47.24,1.91) v1(48.13,44.91) v1(48.22,35.81) v1(49.15,74.3) v1(49.15,22.86) v1(49.15,19.05) v1(49.15,15.24) v1(49.15,11.43) v1(49.15,7.62) v1(49.15,3.81) v1(50.01,59.54) v1(50.59,41.96) v1(50.8,26.19) v1(51.05,76.2) v1(51.05,72.39) v1(51.05,64.77) v1(51.05,24.77) v1(51.05,20.96) v1(51.05,17.14) v1(51.05,13.33) v1(51.05,9.53) v1(51.05,5.71) v1(51.36,47.12) v1(51.56,56.52) v1(51.56,53.98) v1(51.56,51.69) v1(51.56,48.9)
3P3VDD: length 13
  TOP w0.305: 2.03,44.45 1.91,44.45 1.84,44.39 C31.2 v1(1.52,45.47)
  TOP w0.508: 2.03,44.45 3.94,44.45 ; U6.8 v1(7.37,46.99)
  BOTTOM w0.203: P1.9 v1(31.29,76.45)
  BOTTOM w0.508: v1(1.52,45.47) 3.48,45.47 5,46.99 v1(7.37,46.99)
CT_LASER: length 57.5
  TOP w0.203: v1(7.62,60.71) 12.62,60.71 18.03,66.12 18.03,69.85 19.18,70.99 20.65,70.99 22.24,72.58 27.29,72.58 27.74,72.14 29.85,72.14 v1(31.12,73.41) ; R41.2 6.63,48.42 6.63,45.19 v1(7.37,44.45) U6.6
  BOTTOM w0.203: v1(7.62,60.71) 6.86,59.94 6.86,53.34 8.13,52.07 8.13,45.21 v1(7.37,44.45) ; v1(31.12,73.41) 30.79,73.73 P1.11
DS1: length 22.9
  TOP w1.016: 5.87,33.44 LD1.A 3.56,34.74
  BOTTOM w0.508: 6.43,31.75 D5.C ; D5.C 5.42,32.6 ; D5.C 4.57,31.75 ; D5.C 5.42,30.9 ; C5.2 4.61,29.38 ; C5.2 5.79,30.23 ; C5.2 7.02,29.38 ; 7.96,29.64 C9.2 ; C9.2 7,31.1 ; C9.2 8.86,31.1 ; 7.98,28.98 C27.2 9.21,27.83
  BOTTOM w0.635: 7.01,33.27 R5.2 7.87,34.12
  BOTTOM w1.524: 6.69,37.34 C20.P 5.14,33.82
  vias: v1(6.15,32.77) v1(6.86,33.27) v1(7.11,34.54)
DS2: length 23
  TOP w1.016: 47.02,30.57 LD2.A 49.28,29.31
  BOTTOM w0.508: C15.2 43.86,32.47 ; C15.2 45.76,32.47 ; C15.2 44.85,34.02 ; D10.C 46.28,32.05 ; D10.C 48.21,32.05 ; D10.C 47.31,31.3 ; D10.C 47.31,32.82 ; 45.97,30.23 R13.2 44.86,29.32
  BOTTOM w0.762: 45.82,34.46 C16.2 ; C16.2 46.99,33.6 ; C16.2 48.16,34.46 ; 45.63,35.27 C28.2 44.42,34.21
  BOTTOM w1.524: 47.51,28.77 C21.P 45.96,25.25
  vias: v1(46.2,30.86) v1(46.23,29.97) v1(46.23,29.08)
DS3: length 24.4
  TOP w1.016: 26.29,46.2 LD3.A 24.03,47.46
  BOTTOM w0.254: 22.6,47.06 C13.2
  BOTTOM w0.508: 23.62,50.04 23.62,50.8 23.33,51.09 C30.2 21.76,51.09 ; 24.16,47.85 D9.C ; D9.C 24.99,48.61 ; D9.C 25.81,47.85 ; D9.C 24.99,47.02 ; C13.2 23.55,48.5 ; C13.2 21.65,48.5 ; C13.2 22.73,48.37 22.73,46.94 ; C13.2 22.6,49.91 ; 21.3,47.57 21.58,47.29 21.58,46.52 R11.2 22.61,46.36 v1(22.73,46.48) v1(23.65,46.48) ; 25.09,49.59 C14.2
  BOTTOM w0.762: C23.P 21.08,56.2 21.08,53.47
  vias: v1(23.75,47.5)
DS4: length 27.8
  TOP w1.016: 28.42,16.8 LD4.A 26.16,18.06
  BOTTOM w0.508: D6.C 28.19,16 ; D6.C 27.39,15.28 ; D6.C 26.54,16 ; D6.C 27.39,16.73 ; C10.2 30.83,15.59 ; C10.2 29.8,17.19 ; C10.2 28.74,15.59 ; 30.92,13.14 C29.2 ; 30.65,17.18 R6.2 29.72,18.03 v1(29.59,17.91)
  BOTTOM w0.635: C22.P 30.42,7.54 ; C22.P 30.42,5.59 ; C22.P 32.13,6.86 ; 30.42,7.54 30.42,8.95 31.01,9.55 31.01,10.57 ; 30.42,7.54 31.05,8.18 32.21,8.18 ; 30.42,5.59 30.42,3.11 ; 30.42,5.59 30.92,5.08 32.11,5.08
  BOTTOM w0.762: C6.2 27.65,14.22
  vias: v1(28.66,17.84) v1(29.17,17.21)
I2C0_SCL: length 58.3
  TOP w0.203: v1(32.29,76.5) 32.29,75.78 31.19,74.68 19.88,74.68 16.19,70.99 4.25,70.99 v1(2.16,68.9) ; 3.94,46.99 3.05,46.99 v1(2.16,47.88)
  BOTTOM w0.203: P1.5 v1(32.29,76.5) ; v1(2.16,68.9) v1(2.16,47.88)
I2C0_SDA: length 57.9
  TOP w0.203: v1(2.16,46.61) 3.05,45.72 3.94,45.72 ; v1(3.75,68.9) 5.36,70.51 16.25,70.51 20.04,74.3 31.24,74.3 v1(32.13,73.41)
  BOTTOM w0.203: v1(32.13,73.41) 31.79,73.75 P1.7 ; v1(2.16,46.61) 2.92,47.37 2.92,68.07 v1(3.75,68.9)
INT_LASER: length 54.8
  TOP w0.203: v1(7.62,61.85) 8.13,61.34 12.45,61.34 17.55,66.45 17.55,69.91 19.02,71.37 20.45,71.37 22.03,72.96 27.65,72.96 27.97,72.64 29.21,72.64 v1(29.97,73.41) ; R40.2 v1(8.76,48.01) ; v1(7.37,43.18) U6.5
  BOTTOM w0.203: P1.13 30.29,73.72 v1(29.97,73.41) ; v1(7.37,43.18) 8.76,44.58 v1(8.76,48.01) 8.76,52.2 7.49,53.47 7.49,59.56 8.25,60.33 8.25,61.21 v1(7.62,61.85)
IOVDD: length 48.7
  TOP w0.203: v1(4.65,66.65) 12.93,66.65 19.69,73.41 v1(28.7,73.41)
  TOP w0.254: R40.1 R41.1 v1(7.37,51.56)
  BOTTOM w0.203: v1(4.65,66.65) 4.06,66.07 4.06,54.86 v1(7.37,51.56) ; P1.15 29.79,74.12 29.07,73.41 v1(28.7,73.41)
LD1: length 102.9
  TOP w0.305: v3(16.8,66.89) 15.49,65.58 6.35,65.58 6.05,65.28 6.05,61.37 5.73,61.06 3.61,61.06 3.25,60.7 3.25,60.17 3.58,59.84 5.74,59.84 6.05,59.53 6.05,58.9 5.74,58.59 3.25,58.59 2.87,58.21 2.87,57.68 3.17,57.37 5.69,57.37 5.99,57.07 5.99,56.46 5.69,56.15 2.29,56.15 1.98,55.85 1.98,55.24 2.29,54.93 5.64,54.93 5.94,54.63 5.94,54.02 5.64,53.71 2.29,53.71 1.98,53.41 1.98,52.8 2.29,52.5 5.54,52.5 5.84,52.19 5.84,51.56 5.54,51.26 2.21,51.26 1.91,50.95 1.91,50.34 2.21,50.04 5.54,50.04 5.87,49.71 5.87,40.92 3.81,38.86 1.93,38.86 0.89,37.82 0.89,28.45 1.68,27.66 1.68,26.14 1.07,25.53 1.07,17.2 1.37,16.89 v3(2.29,16.89)
  BOTTOM w0.305: U1.2 2.42,17.91 R1.1 2.29,16.89 v3(2.29,16.89) ; v3(16.8,66.89) 17.87,66.89 18.78,67.8 P1.60
LD2: length 102.9
  TOP w0.305: v3(20.8,67.81) 23.61,67.81 24.87,66.55 31.37,66.55 35.41,62.51 44.03,62.51 44.88,61.65 46.1,61.65 46.41,61.35 46.41,60.74 46.1,60.44 45.52,60.44 45.21,60.13 45.21,58.55 45.52,58.24 50.34,58.24 50.65,57.94 50.65,57.43 50.34,57.12 45.52,57.12 45.21,56.82 45.21,56.21 45.52,55.91 50.29,55.91 50.6,55.6 50.6,54.99 50.29,54.69 45.52,54.69 45.21,54.38 45.21,53.77 45.52,53.47 50.29,53.47 50.6,53.16 50.6,52.55 50.29,52.25 44.48,52.25 44.17,51.94 44.17,51.33 44.48,51.03 50.39,51.03 50.7,50.72 50.7,50.11 50.39,49.81 44.12,49.81 43.81,49.5 43.81,48.9 44.12,48.59 44.85,48.59 45.15,48.29 45.15,47.22 45.45,46.91 46.06,46.91 46.37,47.22 46.37,48.29 46.67,48.59 47.28,48.59 47.59,48.29 47.59,47.22 47.89,46.91 48.5,46.91 48.81,47.22 48.81,48.29 49.11,48.59 49.96,48.59 50.27,48.29 v3(50.27,47.04)
  BOTTOM w0.305: v3(20.8,67.81) 20.78,67.83 P1.52 ; v3(50.27,47.04) 50.27,46.25 R10.1 50.26,46 U4.2
LD3: length 102.9
  TOP w0.305: v3(24.92,65.41) 31.29,65.41 33.63,63.07 33.63,59.69 33.93,59.39 38.33,59.39 38.63,59.08 38.63,58.34 38.33,58.04 33.35,58.04 33.05,57.73 33.05,57.25 33.35,56.95 38.51,56.95 38.81,56.64 38.81,56.03 38.51,55.73 33.48,55.73 33.17,55.42 33.17,54.81 33.48,54.51 38.51,54.51 38.81,54.2 38.81,53.59 38.51,53.29 33.48,53.29 33.17,52.98 33.17,52.37 33.48,52.07 38.63,52.07 38.93,51.77 38.93,51.33 38.63,51.03 32.99,51.03 32.69,50.72 32.69,50.11 32.99,49.81 38.43,49.81 38.73,49.5 38.73,49.07 38.43,48.77 31.55,48.77 30.63,49.68 30.63,62.28 30.1,62.81 v3(28.29,62.81)
  BOTTOM w0.305: P1.44 22.78,67.54 v3(24.92,65.41) ; v3(28.29,62.81) 28.29,62.14 R9.1 28.29,61.87 U3.2
LD4: length 103
  TOP w0.305: v1(42.42,38.73) 41.15,37.47 41.15,22.91 29.85,11.61 29.85,6.22 v3(25.53,1.91)
  BOTTOM w0.305: P1.36 24.79,70.02 25.88,71.12 32.96,71.12 34.12,69.95 42.09,69.95 48.03,64.01 48.03,60.53 48.9,59.66 48.9,49.71 42.42,43.23 v1(42.42,38.73) ; v3(25.53,1.91) 24.5,1.91 R2.1 24.61,2.11 U2.2
LD_SD1: length 139.6
  TOP w0.203: v2(41.26,56.49) 41.26,47.34 43.08,45.52 49.1,45.52 49.26,45.35 v2(49.27,45.35) ; v2(3.24,18.57) 3.55,18.25 7.64,18.25 10.57,21.18 10.57,25.4 8.84,27.13 8.84,33.45 10.29,34.9 10.29,41.71 11.13,42.55 11.13,57.99 18.85,65.71 18.85,68.48 19.66,69.29 24.1,69.29 25.93,71.12 32.43,71.12 33.15,71.84 33.15,75.56 v2(33.78,76.2) 44.07,76.2 48.39,71.88 48.39,66.55 v2(45.47,63.63)
  BOTTOM w0.203: v2(41.26,56.49) 44.02,56.49 45.47,57.94 v2(45.47,63.63) ; v2(3.24,18.57) 3.07,18.74 U1.1 ; v2(49.27,45.35) 49.61,45.01 U4.1 ; P1.1 33.29,76.02 33.47,76.2 v2(33.78,76.2)
LD_SD2: length 160.9
  TOP w0.203: v2(48.51,65.41) 48.51,60.25 47.42,59.16 v2(46.41,59.16) ; v2(27.58,61.23) 27.58,57.38 29.85,55.12 29.85,48.69 31.72,46.81 38.96,46.81 40.23,48.08 v2(40.23,55.42) ; v2(10.57,26.39) 9.65,27.3 9.65,33.27 11,34.62 11,41.02 16.66,46.69 16.66,48.18 19.1,50.62 19.1,61.04 v3(20.59,62.53) ; v2(25.26,2.72) v2(22.05,5.92)
  BOTTOM w0.203: P1.3 32.79,76.15 33.79,77.14 43.76,77.14 48.51,72.39 v2(48.51,65.41) ; v3(20.59,62.53) 21.56,63.5 27.1,63.5 27.69,62.92 27.69,61.33 v2(27.58,61.23) ; v2(10.57,26.39) 10.57,11.96 14.12,8.41 19.57,8.41 v2(22.05,5.92) ; U2.1 v2(25.26,2.72) ; v2(46.41,59.16) 46.41,57.68 44.48,55.75 40.56,55.75 v2(40.23,55.42)
  BOTTOM w0.305: v2(27.58,61.23) 27.64,61.17 U3.1
LD_SUPPLY: length 9.2
  BOTTOM w0.508: R22.2 42.62,62.05 ; R5.1 v1(10.67,33.27) ; R6.1 v1(33.5,18.03)
  BOTTOM w0.635: R13.1 v1(42.13,30.23) ; v1(42.62,63.55) 42.62,62.26 R22.2 43.45,62.15 44.07,61.53 v1(44.07,61.28) ; v1(18.95,46.48) 19.08,46.36 R11.1 ; 42.62,62.05 v1(42.62,60.73)
TAL1: length 69.9
  TOP w0.305: v1(18.67,64.31) 16.56,62.2 16.56,53.77 17.83,52.5 v1(17.83,50.6)
  BOTTOM w0.305: R25.2 1.71,41.03 2.74,42.06 8.25,42.06 10.59,44.4 10.59,45.42 10.9,45.72 16.21,45.72 16.51,46.03 16.51,46.64 16.18,46.97 11.61,46.97 11.3,47.27 11.3,47.88 11.61,48.19 16.18,48.19 16.48,48.49 16.48,49.05 16.18,49.35 11.64,49.35 11.33,49.66 11.33,50.29 11.64,50.6 v1(17.83,50.6) ; P1.56 19.78,66.54 18.67,65.43 v1(18.67,64.31)
TAL2: length 70
  TOP w0.305: v3(50.79,27.3) 46.05,27.3 44.42,28.93 44.42,33.93 v3(43.03,35.33)
  BOTTOM w0.305: P1.48 21.78,65.72 22.89,64.62 29.36,64.62 32.4,61.58 32.4,56.37 32.73,56.04 34.09,56.04 34.39,55.74 34.39,55.1 34.09,54.8 32.65,54.8 32.32,54.47 32.32,53.91 32.65,53.58 34.52,53.58 34.82,53.27 34.82,52.71 34.5,52.38 32.73,52.38 32.4,52.05 32.4,47.41 43.03,36.78 v3(43.03,35.33) ; R26.2 v3(50.79,27.3)
TAL3: length 69.9
  TOP w0.305: v1(30.22,46.67) 31.12,45.77 37.59,45.77 v1(38.48,44.88)
  BOTTOM w0.305: P1.40 23.78,67.5 25.91,65.38 30.43,65.38 31.12,64.69 32.66,64.69 34.54,62.81 36.63,62.81 37.31,62.13 37.31,53.59 39.07,51.84 44.28,51.84 44.58,51.53 44.58,51 44.28,50.69 37.82,50.69 37.49,50.36 37.49,49.78 37.8,49.48 44.39,49.48 44.69,49.17 44.69,48.61 44.26,48.18 39.01,48.18 38.48,47.65 v1(38.48,44.88) ; v1(30.22,46.67) R30.2
TAL4: length 70
  TOP w0.305: v3(26.01,70.08) 24.56,68.63 20.45,68.63 19.66,67.84 19.66,64.97 21.39,63.25 21.39,61.49 19.94,60.05 19.94,48.64 11.96,40.67 11.96,25.7 v3(21.67,16)
  BOTTOM w0.305: P1.32 25.79,69.86 v3(26.01,70.08) ; v3(21.67,16) R29.2
UNNAMED_4_ADP36X4_I6_INB: length 2.1
  BOTTOM w0.305: U1.4 1.12,17.95 R1.2
UNNAMED_4_ADP36X4_I6_OUTA: length 2.9
  BOTTOM w0.305: R7.1 2.48,26.92 R42.2 2.48,25.21 2.42,25.15 U1.7
UNNAMED_4_ADP36X4_I6_OUTB: length 2.3
  BOTTOM w0.305: R42.1 1.12,25.44 U1.5
UNNAMED_4_ADP36X4_I6_VDD: length 6
  TOP w0.305: C1.2 1.98,25.53 v3(1.77,25.31)
  BOTTOM w0.305: U1.6 v3(1.77,25.31)
  BOTTOM w0.508: C3.2 5.3,22.07 v1(6.5,22.07) R31.2 7.54,22.21 v1(7.54,22.99)
UNNAMED_4_ADP36X4_I26_INB: length 2.1
  BOTTOM w0.305: U2.4 23.31,2.1 R2.2
UNNAMED_4_ADP36X4_I26_OUTA: length 3.1
  BOTTOM w0.305: U2.7 24.61,9.81 24.38,10.04 R44.2 24.38,11.28 R8.1
UNNAMED_4_ADP36X4_I26_OUTB: length 2.5
  BOTTOM w0.305: R44.1 23.75,10.28 23.31,9.85 U2.5
UNNAMED_4_ADP36X4_I26_VDD: length 7.2
  TOP w0.305: C2.2 24.1,9.75 v3(23.96,9.61)
  BOTTOM w0.305: U2.6 v3(23.96,9.61)
  BOTTOM w0.508: v1(21.67,3.17) 21.67,3.93 R33.2 21.67,4.2 v1(21.67,4.95) ; v1(27.58,7.37) C4.2 v1(26.3,6.24)
UNNAMED_4_ADP36X4_I59_INB: length 2
  BOTTOM w0.305: U3.4 29.59,61.83 R9.2
UNNAMED_4_ADP36X4_I59_OUTA: length 3.1
  BOTTOM w0.305: U3.7 28.29,53.6 R45.2 28.5,52.73 R12.1
UNNAMED_4_ADP36X4_I59_OUTB: length 2.5
  BOTTOM w0.305: U3.5 29.59,53.85 R45.1
UNNAMED_4_ADP36X4_I59_VDD: length 7.5
  TOP w0.305: v3(28.94,54.41) 28.24,54.41 28.12,54.28 C7.2
  BOTTOM w0.305: U3.6 v3(28.94,54.41)
  BOTTOM w0.508: v1(25.37,56.41) C11.2 v1(26.67,57.67) ; v1(26.09,62.76) 25.95,62.63 R34.2 v1(27.03,61.75)
UNNAMED_4_ADP36X4_I77_INB: length 2.2
  BOTTOM w0.305: U4.4 51.56,45.7 R10.2
UNNAMED_4_ADP36X4_I77_OUTA: length 2.9
  BOTTOM w0.305: U4.7 50.26,38.21 50.23,38.18 R43.2 50.23,36.96 R14.1
UNNAMED_4_ADP36X4_I77_OUTB: length 2.4
  BOTTOM w0.305: R43.1 50.86,37.77 51.56,38.47 U4.5
UNNAMED_4_ADP36X4_I77_VDD: length 6
  TOP w0.305: C8.2 50.65,38.35 v3(50.9,38.61)
  BOTTOM w0.305: v3(50.9,38.61) 50.91,38.62 U4.6
  BOTTOM w0.508: C12.2 47.64,41.83 R32.2 45.58,41.08 v1(45.72,40.94)
UNNAMED_4_ADP250X_I213_EN: length 13.2
  TOP w0.203: 38.48,66.08 U5.6
  TOP w0.254: U5.8 40.69,65.54 40.32,65.17 C25.1
  TOP w0.305: C25.1 40.03,64.52
  TOP w0.508: 40.03,64.52 38.99,64.52 38.48,65.02 38.48,66.08 37.29,66.08 36.45,66.93 R36.1 37.94,68.97 C24.2 38.14,69.16 39.12,69.16
UNNAMED_4_ADP250X_I213_FB: length 4.3
  TOP w0.203: v2(41.91,65.28) 41.89,65.28 41.69,65.48 U5.10
  BOTTOM w0.203: R35.2 R37.1 41.94,66.14 41.73,65.94 41.73,65.46 v2(41.91,65.28)
UNNAMED_4_ADP250X_I213_SW1: length 3.1
  TOP w0.254: U5.4 40.19,70.17 39.36,71.01 L1.1
UNNAMED_4_ADP250X_I213_SW2: length 3
  TOP w0.254: U5.2 41.19,70.4 41.77,70.98 L1.2
UNNAMED_4_ADP250X_I213_VOUT: length 8.4
  TOP w0.508: v1(44.86,66.14) 45.63,66.91 R39.1 45.59,69.53 C26.2 43.42,69.14 42.19,69.14
  BOTTOM w0.508: R37.2 v1(44.86,66.14)
UNNAMED_4_DIOZNR_I124_P: length 8.6
  TOP w0.381: LD1.C 3.28,31.05 v2(3.28,29.69)
  BOTTOM w0.203: Q1.5 3.68,29.44 3.43,29.69 v2(3.28,29.69) 3.09,29.69 2.88,29.49 Q1.3
  BOTTOM w0.305: R25.1 3.22,33.6 D5.A
  BOTTOM w0.381: v2(3.28,29.69) 3.28,31.69 D5.A
UNNAMED_4_DIOZNR_I125_P: length 12.5
  TOP w0.381: v2(23.75,14.6) 26.07,14.6 LD4.C
  BOTTOM w0.203: Q2.5 26.05,13.96 25.4,14.6 v2(23.75,14.6) 23.75,14.43 24.05,14.12 24.99,14.12 25.25,13.87 Q2.3
  BOTTOM w0.381: R29.1 D6.A 25.19,15.92 24.51,15.24 24.13,15.24 23.75,14.86 v2(23.75,14.6)
UNNAMED_4_DIOZNR_I126_P: length 8.6
  TOP w0.381: v2(49.25,34.24) 49.25,32.7 LD2.C
  BOTTOM w0.203: Q4.3 49.62,34.51 49.35,34.24 v2(49.25,34.24) 49.15,34.24 48.82,34.57 Q4.5
  BOTTOM w0.305: R26.1 49.79,31.78 D10.A
  BOTTOM w0.381: v2(49.25,34.24) 49.25,32.32 D10.A
UNNAMED_4_DIOZNR_I127_P: length 12.5
  TOP w0.381: LD3.C 26.45,49.4 v2(28.7,49.4)
  BOTTOM w0.203: Q3.3 27.55,50.35 27.81,50.09 28.35,50.09 28.7,49.73 v2(28.7,49.4) 27.56,49.4 26.75,50.21 Q3.5
  BOTTOM w0.305: R30.1 D9.A
  BOTTOM w0.381: v2(28.7,49.4) 28.7,49.1 28.32,48.72 27.57,48.72 27.19,48.34 D9.A
UNNAMED_4_RES_I11_N2: length 1
  BOTTOM w0.203: Q1.1 2.48,27.8 2.41,27.73 R7.2
UNNAMED_4_RES_I44_N2: length 1
  BOTTOM w0.203: R8.2 24.85,12.38 Q2.1
UNNAMED_4_RES_I53_N2: length 5.4
  TOP w0.381: v2(2.34,29.68) 2.34,28.82 v2(3.28,27.87)
  BOTTOM w0.203: Q1.4 v2(3.28,27.87) ; v2(2.34,29.68) 2.48,29.54 2.48,29.44 2.48,29.43 Q1.2
  BOTTOM w0.508: v2(3.28,27.87) 3.28,27.17 R3.2
UNNAMED_4_RES_I54_N2: length 5.7
  TOP w0.381: v2(25.65,12.14) 24.94,12.14 24.13,12.95 v2(24.13,13.21)
  BOTTOM w0.203: Q2.2 24.85,13.36 24.65,13.56 24.36,13.56 24.13,13.34 v2(24.13,13.21) ; v2(25.65,12.14) Q2.4
  BOTTOM w0.508: R4.2 25.65,12.14 v2(25.65,12.14)
UNNAMED_4_RES_I70_N2: length 4.8
  TOP w0.381: v2(28.57,50.93) 28.23,50.93 27.34,51.82 v2(27.15,51.82)
  BOTTOM w0.203: Q3.2 28.35,50.7 v2(28.57,50.93) ; v2(27.15,51.82) 27.15,51.82 Q3.4
  BOTTOM w0.508: R15.2 27.15,53.16 v2(27.15,51.82)
UNNAMED_4_RES_I73_N2: length 1.1
  BOTTOM w0.203: R12.2 27.95,51.54 Q3.1
UNNAMED_4_RES_I87_N2: length 5.1
  TOP w0.381: v3(49.22,35.88) 49.22,35.58 50.33,34.47 v2(50.48,34.47)
  BOTTOM w0.203: v2(50.48,34.47) 50.29,34.47 50.02,34.74 Q4.2 ; Q4.4 v3(49.22,35.88)
  BOTTOM w0.381: v3(49.22,35.88) 48.83,36.27 R16.2
UNNAMED_4_RES_I90_N2: length 1.1
  BOTTOM w0.203: Q4.1 50.02,36.03 50.22,36.23 50.27,36.23 R14.2
VLD_BRD: length 23.6
  BOTTOM w0.305: P1.16 29.79,67.79 ; 28.29,67.88 P1.22 ; P1.14 30.29,67.78 v1(30.1,67.59) ; P1.8 31.79,67.76 v1(31.62,67.59) ; P1.10 31.29,67.89 ; P1.20 28.79,67.8 v1(28.57,67.59) ; P1.2 33.29,67.73 v1(33.15,67.59) ; 32.79,67.61 P1.4 ; v1(30.86,67.59) 30.79,67.66 P1.12 ; P1.6 32.29,67.68 v1(32.38,67.59) ; P1.18 29.29,67.64 v1(29.34,67.59) ; 27.79,67.59 P1.24
  BOTTOM w0.381: C18.2 v1(35.31,65.81)
  BOTTOM w0.508: v1(38.48,61.77) 38.86,62.15 R22.1 39.83,62.05 ; D8.C 33.26,65.87 33.43,66.04 v1(34.23,66.04) ; 39.83,62.05 v1(39.83,63.55) ; 39.83,62.05 v1(39.83,60.81)
  vias: v1(27.81,67.59)

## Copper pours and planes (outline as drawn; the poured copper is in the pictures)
5V_LD on L3_PWR: 0.51,0.51 0.51,20.38 7.62,20.38 8.45,21.2 8.45,25.91 7.62,26.73 0.51,26.73 0.51,77.47 22.42,77.47 22.42,69.08 23.49,68.01 45.47,68.01 46.29,68.83 46.29,77.47 52.07,77.47 52.07,42.23 45.21,42.23 44.39,41.41 44.39,37.84 45.08,37.15 52.07,37.15 52.07,0.51 ; 2 cut-outs
5VDD_CON on L3_PWR: 23.75,68.64 23.05,69.35 23.05,77.47 45.66,77.47 45.66,69.09 45.21,68.64
AGND on TOP: 1.2,77.42 52.04,77.42 52.04,0.51 0.53,0.51 0.53,26.48 0.68,26.37 0.85,26.43 0.89,26.47 0.89,27.33 0.85,27.37 0.68,27.43 0.53,27.32 0.53,77.42 0.53,77.29 0.65,77.11 0.86,77.13 0.99,77.21 1.13,77.27 1.2,77.3 ; 24 cut-outs
AGND on BOTTOM: 0.53,77.44 52.04,77.44 52.04,0.51 0.53,0.51 0.53,18.23 0.67,18.23 0.7,18.29 0.74,18.35 0.79,18.39 0.79,18.73 0.75,18.76 0.72,18.79 0.7,18.82 0.67,18.87 0.53,18.87 ; 14 cut-outs
AGND on L2_GND: 52.07,77.47 0.51,77.47 0.51,0.51 52.07,0.51
AGND on L5_GND: 52.07,77.47 0.51,77.47 0.51,0.51 52.07,0.51
(no net) on BOTTOM: 26.14,14.5 26.14,17.27 26.85,17.98 28.5,17.98 28.78,18.26 30.73,18.26 30.73,18.21 32,16.94 32,13.33 32.64,12.7 32.64,2.92 32.26,2.54 30.1,2.54 29.77,2.87 29.77,3.35 29.97,3.56 29.97,11.68 27.81,13.84 26.8,13.84
3P3VDD on L4_PWR: 0.51,44.51 0.51,77.47 31.94,77.47 31.94,74.68 31.24,73.98 27.55,73.98 26.61,73.03 26.61,65.54 26.16,65.09 7.11,65.09 5.91,63.89 5.91,45.09 5.33,44.51
DS1 on TOP: 7.62,32.51 7.62,35.31 7.49,35.43 1.78,35.43 1.65,35.31 1.65,34.72 1.78,34.59 1.78,34.37 1.75,34.34 1.65,34.34 1.65,32.54 5.69,32.54 5.84,32.38 7.49,32.38
DS1 on BOTTOM: 4.19,29.21 4.19,33.66 4.7,34.16 4.7,38.1 7.37,38.1 7.49,37.97 7.49,35.36 8.48,34.37 8.48,32 9.6,30.89 9.6,27.36 9.3,27.05 7.75,27.05 7.24,27.56 7.24,28.7 6.73,29.21 4.83,29.21 4.7,29.08 4.32,29.08
DS2 on TOP: 45.21,31.5 45.21,28.7 45.72,28.19 50.67,28.19 51.18,28.7 51.18,29.29 51.05,29.41 51.05,29.64 51.08,29.67 51.18,29.67 51.18,31.47 47.14,31.47 46.99,31.62 45.34,31.62
DS2 on BOTTOM: 44.58,24.51 44.58,29.34 44.7,29.46 44.7,30.81 45.49,30.81 45.49,30.66 45.69,30.66 45.69,31.52 45.49,31.52 45.49,31.37 44.32,31.37 43.43,32.26 43.43,34.16 43.81,34.54 43.81,35.69 45.85,35.69 45.97,35.56 45.97,35.05 46.1,34.93 48.26,34.93 48.77,34.42 48.77,28.83 48.51,28.58 48.51,24.89 48.13,24.51 46.1,24.51 45.85,24.26 44.83,24.26
DS3 on TOP: 22.23,48.39 22.23,45.59 22.35,45.47 28.07,45.47 28.19,45.59 28.19,46.18 28.07,46.3 28.07,46.53 28.09,46.56 28.19,46.56 28.19,48.36 24.15,48.36 24,48.51 22.35,48.51
DS3 on BOTTOM: 21.33,47.2 21.33,46.36 22.35,46.36 22.61,46.1 25.91,46.1 26.11,46.3 26.11,49.53 25.91,49.73 25.91,49.91 25.78,50.04 24,50.04 23.62,50.42 23.62,51.31 23.37,51.56 22.23,51.56 21.84,51.94 21.84,53.72 21.72,53.85 20.45,53.85 20.32,53.72 20.32,48.21
DS4 on BOTTOM (solid shape): outline of 252 points within 26.14,2.54 32.64,18.26
DS4 on TOP: 30.23,15.88 30.23,18.67 30.1,18.8 24.38,18.8 24.26,18.67 24.26,18.08 24.38,17.96 24.38,17.73 24.36,17.7 24.26,17.7 24.26,15.9 28.3,15.9 28.45,15.75 30.1,15.75
LD_SUPPLY on L4_PWR: 0.51,0.51 0.51,43.88 5.59,43.88 6.54,44.83 6.54,63.62 7.37,64.45 32.25,64.45 32.96,63.75 32.96,60.57 33.78,59.75 41.41,59.75 42.1,60.45 42.1,63.88 42.42,64.2 52.07,64.2 52.07,0.51
UNNAMED_4_ADP36X4_I6_VDD on L3_PWR: 0.51,21.02 0.51,26.1 7.36,26.1 7.81,25.65 7.81,21.47 7.36,21.02
UNNAMED_4_ADP36X4_I26_VDD on L3_PWR: 21.59,2.6 21.15,3.05 21.15,9.77 21.59,10.22 27.81,10.22 28.13,9.9 28.13,3.05 27.68,2.6
UNNAMED_4_ADP36X4_I59_VDD on L3_PWR: 24.9,52.77 24.45,53.22 24.45,57.91 25.59,59.05 25.59,63.11 26.04,63.56 32.76,63.56 33.21,63.11 33.21,53.22 32.76,52.77
UNNAMED_4_ADP36X4_I77_VDD on L3_PWR: 45.34,37.78 45.02,38.1 45.02,41.14 45.47,41.59 52.07,41.59 52.07,37.78
VLD_BRD on BOTTOM: 27.43,67.82 27.43,65.66 27.56,65.53 30.61,65.53 30.73,65.66 30.73,66.93 30.86,67.06 33.53,67.06 33.66,67.18 33.66,67.82 33.53,67.95 27.56,67.95
VLD_BRD on L4_PWR: 34.04,60.39 33.59,60.84 33.59,64.01 32.52,65.09 27.69,65.09 27.24,65.54 27.24,72.77 27.82,73.34 31.5,73.34 32.58,74.42 32.58,77.47 52.07,77.47 52.07,64.83 42.16,64.83 41.47,64.14 41.47,60.71 41.14,60.39

Small or netless copper shapes (teardrops, artwork), in the pictures only: 2 on TOP

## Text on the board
Ref Des/Assembly Bottom: A | C | 3 | 2 | 1
Ref Des/Silkscreen Bottom: A | C | 08-051355 REV C Z | SECONDARY SIDE
User.Comments: SEE DETAIL A | 4 PLACES
Ref Des/Assembly Top: A | C
Ref Des/Silkscreen Top: A | C | PRIMARY SIDE | 08-051355 REV C Z | 96ToF LASER1 | 987126A
PAGE_OUTLINE: 06NOV18 | B | C | AS PER ECR-085793 | AS PER ECR-088821 | 27MAR19 | 27JUN19 | MBANCISO | CUSTOMER EVAL Z
DIMENSION: REF | DIA MAX
DISPLAY_BOTTOM: 08-      -11
User.12: 15.    BOARDS TO BE SHIPPED IN ARRAYS
User.45: FIGURE | SIZE | 8.0 | 12.0 | 65.0 | 40.0 | 120.0 | PLATED | NON-PLATED | FINISHED HOLES IN MILS | ALL UNITS ARE IN MILS | QTY | 49 | 366 | 2 | TOLERANCE/NOTES
